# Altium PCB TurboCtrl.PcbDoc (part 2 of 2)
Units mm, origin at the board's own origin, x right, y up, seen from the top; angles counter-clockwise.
Board outline 40.25 x 40.25 mm, 4 copper layers (Top Layer, GND, SIGNAL, Bottom Layer), stack 1.571 mm thick; 111 components, 99 nets, 426 pads, 163 vias.
Unrouted connection lines stored in the file: 47.
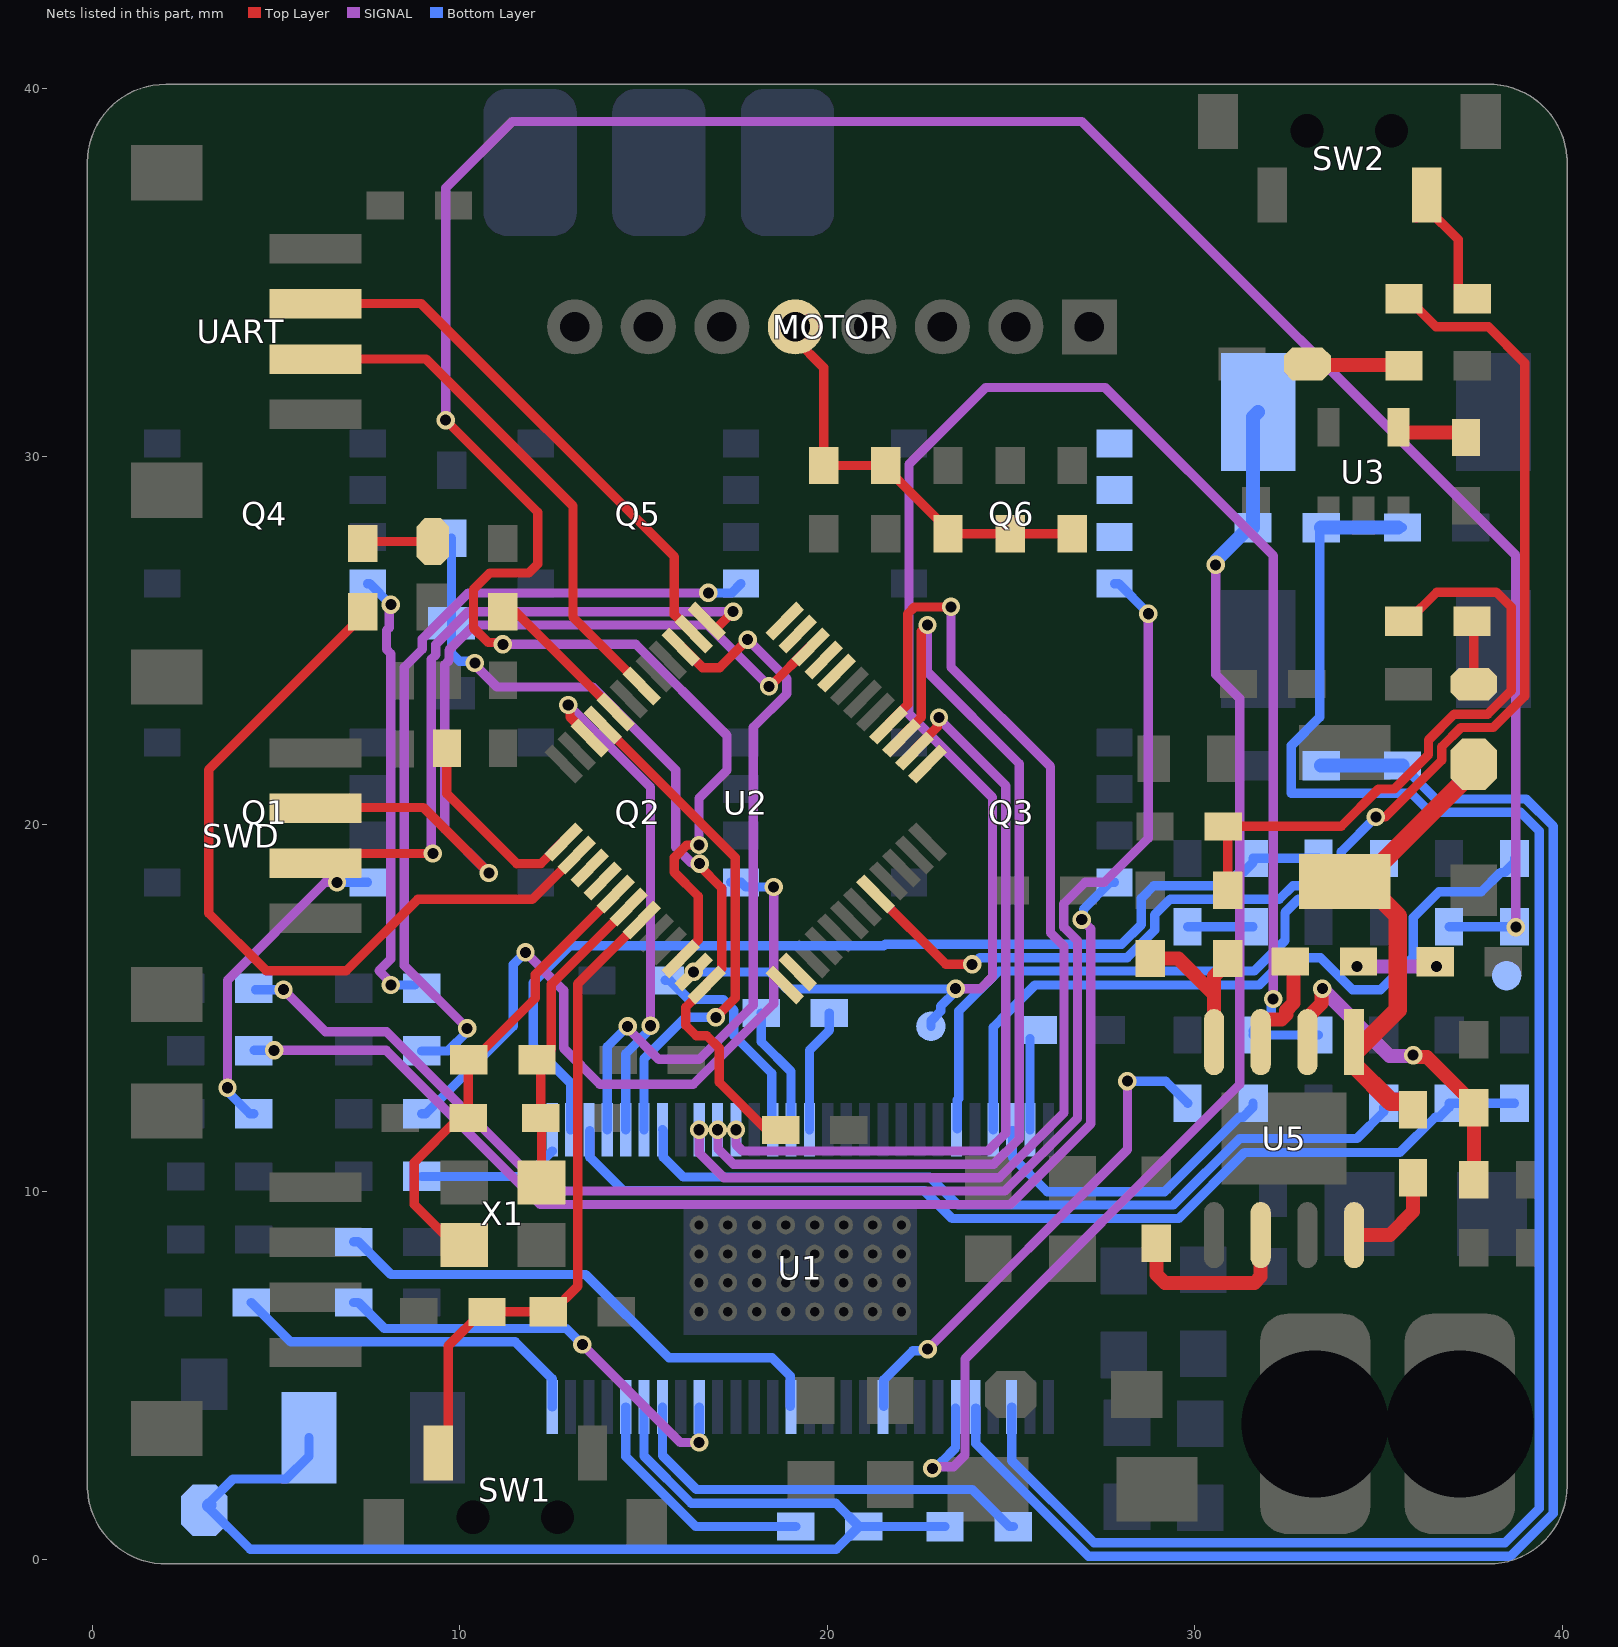
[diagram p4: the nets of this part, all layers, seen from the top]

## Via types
v1: diameter 0.5, hole 0.3, Top Layer to Bottom Layer, tented both sides, 163 vias

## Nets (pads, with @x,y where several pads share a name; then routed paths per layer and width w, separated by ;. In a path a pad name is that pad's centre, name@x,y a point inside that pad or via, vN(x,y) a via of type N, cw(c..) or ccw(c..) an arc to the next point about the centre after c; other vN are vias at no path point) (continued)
M_C_Current: Q6.S R23.2 R24.1 U1.34 | length 35.3
  SIGNAL w0.254: v1(22.86,2.471) 22.907,2.518 23.433,2.518 23.749,2.834 23.749,5.449 31.221,12.921 31.221,23.416 30.569,24.068 v1(30.569,27.051)
  Bottom Layer w0.254: v1(22.86,2.471) 22.927,2.471 23.121,2.666 23.127,2.666 23.49,3.029 U1.34@23.49,4.115
  Bottom Layer w0.381: v1(30.569,27.051) 30.592,27.074 30.592,27.182 31.477,28.067 R24.1@31.585,28.067 31.585,31.071 R23.2@31.725,31.211
MSPI_SCLK: U1.11 U2.26 | length 21.2
  Top Layer w0.254: U2.26@22.376,22.024 22.994,22.642 22.994,22.854 v1(23.041,22.902)
  SIGNAL w0.254: v1(17.516,11.684) 17.516,11.286 17.694,11.108 24.375,11.108 24.859,11.592 24.859,21.047 23.041,22.865 v1(23.041,22.902)
MSPI_SDI: U1.9 U2.28 | length 31.1
  Top Layer w0.254: U2.28@21.669,22.695 21.669,22.731 22.19,23.252 22.19,25.724 22.374,25.908 v1(23.368,25.908)
  SIGNAL w0.254: v1(16.516,11.684) 16.517,11.682 16.517,11.053 17.19,10.38 24.677,10.38 26.442,12.145 26.442,16.677 26.073,17.047 26.073,21.564 23.368,24.269 v1(23.368,25.908)
MSPI_SDO: U1.10 U2.27 | length 27.6
  Top Layer w0.254: U2.27@22.023,22.342 22.023,22.378 22.554,22.909 22.554,25.245 v1(22.726,25.417)
  SIGNAL w0.254: v1@17.029,11.671 17.029,11.166 17.451,10.744 24.526,10.744 25.223,11.441 25.223,21.64 22.726,24.137 v1(22.726,25.417)
  Bottom Layer w0.254: v1(17.016,11.684) U1.10@17.041,11.709
NetC2_1: C2.1 R8.1 U1.2 | length 27.7
  Bottom Layer w0.254: U1.2@13.016,11.684 13.016,12.954 12,13.97 12,15.683 13.004,16.687 21.538,16.687 21.581,16.73 28.007,16.73 28.546,17.269 28.546,17.983 28.883,18.319 30.84,18.319 31.204,18.684 31.312,18.684 31.585,18.957 R8.1@31.585,19.065 ; R8.1@31.585,19.07 C2.1@33.363,19.07
NetC5_1: C5.1 R8.2 | length 1.8
  Bottom Layer w0.254: C5.1@29.807,17.21 R8.2@31.585,17.21
NetC6_2: C6.2 U1.56 | length 9.8
  Bottom Layer w0.254: C6.2@4.33,6.985 5.402,5.913 11.509,5.913 12.516,4.906 U1.56@12.516,4.14
NetC7_1: C7.1 D1.2 L1.1 R16.1 U1.51 | length 32.6
  Bottom Layer w0.254: D1.2@3.175,1.46 3.175,1.397 4.301,0.271 20.248,0.271 C7.1@20.866,0.889 ; D1.2@3.175,1.524 3.832,2.181 5.278,2.181 5.901,2.804 L1.1@5.901,3.304 ; U1.51@15.016,4.14 15.016,2.809 16.301,1.524 20.231,1.524 C7.1@20.866,0.889 ; R16.1@23.203,0.889 C7.1@20.993,0.889 C7.1@20.866,0.889
  Bottom Layer w0.381: D1.2@3.175,1.46 D1.2@3.195,1.48
NetC7_2: C7.2 U1.52 | length 6.8
  Bottom Layer w0.254: U1.52@14.516,4.14 14.516,2.794 16.421,0.889 C7.2@19.139,0.889
NetC8_2: C8.2 U1.48 | length 11.9
  SIGNAL w0.254: v1(13.335,5.842) 16.002,3.175 v1(16.513,3.175)
  Bottom Layer w0.254: C8.2@7.117,6.985 7.244,6.985 7.952,6.277 12.9,6.277 v1(13.335,5.842) ; v1(16.513,3.175) 16.514,3.176 U1.48@16.514,4.139
NetC9_2: C9.2 U1.43 | length 14.2
  Bottom Layer w0.254: C9.2@7.117,8.636 7.244,8.636 8.133,7.747 13.425,7.747 15.694,5.478 18.497,5.478 18.991,4.985 U1.43@18.991,4.166
NetC10_1: C10.1 U1.13 | length 5.9
  Bottom Layer w0.254: C10.1@15.589,15.748 15.716,15.748 16.236,15.228 17.171,15.228 17.459,14.94 17.459,14.255 18.491,13.224 U1.13@18.491,11.709
NetC11_1: C11.1 U1.14 | length 3.5
  Bottom Layer w0.254: C11.1@18.204,14.859 18.204,14.081 19.016,13.269 U1.14@19.016,11.684
NetC11_2: C11.2 U1.15 | length 3.4
  Bottom Layer w0.254: U1.15@19.516,11.684 19.516,13.851 20.059,14.393 C11.2@20.059,14.859
NetC12_2: C12.2 U1.38 | length 13.7
  SIGNAL w0.254: v1(22.733,5.715) 28.167,11.149 v1(28.167,13.005)
  Bottom Layer w0.254: U1.38@21.541,4.166 21.541,4.884 22.325,5.668 22.686,5.668 v1(22.733,5.715) ; v1(28.167,13.005) 29.21,13.005 C12.2@29.807,12.408
NetC13_2: C13.2 U1.23 | length 17
  Bottom Layer w0.254: U1.23@23.541,11.709 23.541,12.494 23.58,12.532 23.58,14.914 24.668,16.002 31.62,16.002 32.451,16.834 32.451,17.592 32.82,17.961 34.038,17.961 34.76,18.684 34.887,18.684 35.141,18.938 C13.2@35.141,19.065
NetC14_2: C14.2 R20.2 U1.33 | length 44.1
  Bottom Layer w0.254: U1.33@24.041,4.115 24.041,3.148 27.107,0.082 38.588,0.082 39.751,1.245 39.751,19.946 39.013,20.684 36.555,20.684 C14.2@35.649,21.59
  Bottom Layer w0.381: R20.2@33.439,21.59 C14.2@35.649,21.59
NetC15_1: C15.1 U1.27 | length 2.5
  Bottom Layer w0.254: U1.27@25.516,11.684 C15.1@25.516,14.166
NetC16_2: C16.2 R24.2 U1.31 | length 52.4
  Bottom Layer w0.254: U1.31@25.016,4.14 25.016,2.688 27.258,0.446 38.437,0.446 39.37,1.379 39.37,19.812 38.862,20.32 36.404,20.32 35.885,20.839 32.628,20.839 32.628,22.138 33.401,22.911 R24.2@33.401,28.029 ; C16.2@35.522,28.067 C16.2@35.649,28.067
  Bottom Layer w0.381: R24.2@33.439,28.067 C16.2@35.522,28.067
NetC31_1: C31.1 U3.4 | length 1.8
  Top Layer w0.381: U3.4@35.537,30.791 35.537,30.764 35.646,30.655 C31.1@37.245,30.655
NetC32_1: C32.1 D2.2 L2.1 U5.1 | length 12.2
  Top Layer w0.5: C32.1@35.941,12.255 35.75,12.446 35.332,12.446 34.333,13.445 34.333,13.759 35.526,14.952 35.526,17.496 34.579,18.443 D2.2@37.592,21.456
NetC32_2: C32.2 U5.8 | length 2.8
  Top Layer w0.381: U5.8@34.333,8.82 35.306,8.82 35.941,9.455 C32.2@35.941,10.376
NetC38_1: C38.1 R26.2 R34.1 | length 16.8
  Top Layer w0.254: R34.1@30.899,18.199 C38.1@30.899,19.812 ; C38.1@30.899,19.939 33.982,19.939 34.999,20.956 35.427,20.956 36.356,21.885 36.356,22.289 37.059,22.992 37.968,22.992 38.608,23.632 38.608,25.908 38.205,26.311 36.582,26.311 35.795,25.524 R26.2@35.687,25.524
NetC39_1: C39.1 R38.1 | length 2.3
  Top Layer w0.381: v1(34.417,16.129) 34.417,16.218 C39.1@34.455,16.256
  SIGNAL w0.381: v1(34.417,16.129) v1(36.576,16.129)
NetC39_2: C39.2 U5.3 | length 2.9
  Top Layer w0.381: U5.3@31.793,14.07 31.793,14.611 31.871,14.69 32.359,14.69 32.488,14.818 32.488,14.933 32.681,15.127 32.681,16.175 C39.2@32.601,16.256
NetLED1_2: LED1.2 R26.1 | length 1.7
  Top Layer w0.254: LED1.2@37.592,23.808 R26.1@37.592,25.473
NetLED2_2: LED2.2 R28.2 | length 1.9
  Top Layer w0.254: R28.2@7.366,27.635 7.417,27.686 LED2.2@9.264,27.686
NetLED3_2: LED3.2 R31.1 | length 2.6
  Top Layer w0.381: LED3.2@33.063,32.519 33.089,32.493 R31.1@35.666,32.493
NetMOTOR_5: MOTOR.5 R2.2 R3.2 R5.1 R6.1 R7.1 | length 11.3
  Top Layer w0.254: MOTOR.5@19.132,33.191 19.901,32.421 R3.2@19.901,29.756 21.485,29.756 21.866,29.375 21.92,29.375 23.394,27.902 R6.1@24.978,27.902 R7.1@26.67,27.902
NetQ1_G: Q1.G R11.1 | length 8.8
  SIGNAL w0.254: v1(3.683,12.827) 3.683,15.755 6.343,18.415 v1(6.663,18.415)
  Bottom Layer w0.254: v1@3.73,12.78 3.73,12.679 4.291,12.118 R11.1@4.399,12.118 ; v1(6.663,18.415) Q1.G@7.494,18.415
NetQ2_G: Q2.G R12.1 | length 20.1
  SIGNAL w0.254: v1(11.792,16.51) 12.827,15.475 12.827,13.905 13.812,12.92 16.352,12.92 18.542,15.11 v1(18.542,18.288)
  Bottom Layer w0.254: R12.1@8.971,12.118 9.079,12.118 11.46,14.498 11.46,16.178 v1(11.792,16.51) ; Q2.G@17.379,18.415 Q2.G@17.654,18.415 17.781,18.288 v1(18.542,18.288)
NetQ3_G: Q3.G R13.1 | length 32.5
  SIGNAL w0.254: v1(4.953,13.843) 8.001,13.843 12.192,9.652 24.978,9.652 27.17,11.844 27.17,17.153 v1(26.924,17.399)
  Bottom Layer w0.254: R13.1@4.414,13.843 v1(4.953,13.843) ; v1(26.924,17.399) 26.971,17.446 26.971,17.686 27.7,18.415 Q3.G@27.814,18.415
NetQ4_G: Q4.G R17.1 | length 12.2
  SIGNAL w0.254: v1@8.128,15.688 7.808,16.008 8.128,16.328 8.128,24.634 8.008,24.754 8.008,25.268 8.081,25.341 8.081,25.922 v1(8.128,25.969)
  Bottom Layer w0.254: Q4.G@7.494,26.543 7.554,26.543 v1(8.128,25.969) ; v1(8.128,15.621) R17.1@8.781,15.621
NetQ5_G: Q5.G R18.1 | length 22.4
  SIGNAL w0.254: v1(10.204,14.443) 8.492,16.155 8.492,24.264 8.982,24.754 8.982,25.036 10.235,26.289 v1(16.764,26.289)
  Bottom Layer w0.254: R18.1@8.971,13.828 9.681,13.828 10.204,14.351 v1(10.204,14.443) ; v1@16.764,26.356 v1(16.764,26.289) 17.4,26.289 Q5.G@17.654,26.543
NetQ6_G: Q6.G R19.1 | length 41.9
  SIGNAL w0.254: v1(5.207,15.494) 6.35,14.351 8.008,14.351 12.343,10.016 24.827,10.016 26.806,11.995 26.806,16.828 26.437,17.197 26.437,17.834 27.018,18.415 27.534,18.415 28.735,19.616 v1(28.735,25.723)
  Bottom Layer w0.254: R19.1@4.444,15.494 v1(5.207,15.494) ; Q6.G@27.814,26.543 27.928,26.543 28.735,25.736 v1(28.735,25.723)
NetR1_1: R1.1 SW2.2 | length 3.5
  Top Layer w0.254: SW2.2@36.033,36.489 36.306,36.762 37.165,35.903 37.165,34.563 37.438,34.29 R1.1@37.546,34.29 R1.1@37.617,34.29
NetR9_2: R9.2 U1.1 | length 3.8
  Bottom Layer w0.254: R9.2@8.971,10.414 11.825,10.414 U1.1@12.516,11.105
NetR10_2: R10.2 R14.1 U1.3 | length 27.9
  Bottom Layer w0.254: U1.3@13.541,11.659 13.541,10.94 14.448,10.033 22.635,10.033 23.397,9.271 29.56,9.271 31.355,11.066 35.577,11.066 36.538,12.027 36.646,12.027 36.919,12.3 R10.2@36.919,12.408 R14.1@38.697,12.408
NetR15_2: R15.2 U1.7 | length 22.1
  Bottom Layer w0.254: U1.7@15.516,11.684 15.541,11.659 15.541,10.94 16.084,10.397 22.786,10.397 23.548,9.635 29.409,9.635 31.221,11.447 34.412,11.447 35.141,12.176 R15.2@35.141,12.3
NetR16_2: R16.2 U1.50 | length 11.7
  Bottom Layer w0.254: U1.50@15.516,4.14 15.516,2.824 16.444,1.895 23.943,1.895 24.949,0.889 R16.2@25.057,0.889
NetR21_2: R21.2 U1.25 | length 20.3
  Bottom Layer w0.254: U1.25@24.516,11.684 24.516,14.472 24.744,14.7 24.744,14.711 25.654,15.621 31.753,15.621 32.498,16.366 33.418,16.366 34.29,15.494 35.052,15.494 35.941,16.383 35.941,17.457 36.645,18.161 37.793,18.161 38.316,18.684 38.424,18.684 38.697,18.957 R21.2@38.697,19.065
NetR25_2: R25.2 U1.26 | length 8.7
  Bottom Layer w0.254: U1.26@25.041,11.659 25.041,10.94 25.982,9.999 29.176,9.999 31.204,12.027 31.312,12.027 31.585,12.3 R25.2@31.585,12.408
NetR29_2: R29.2 U2.44 | length 4.2
  Top Layer w0.254: R29.2@11.176,25.781 11.512,25.781 U2.44@14.244,23.049
NetR32_1: R32.1 R36.2 U5.2 | length 8.5
  Top Layer w0.381: U5.2@33.063,14.741 33.445,15.122 33.445,15.498 v1(33.467,15.521) ; v1(35.941,13.716) 35.941,13.669 36.312,13.669 37.592,12.389 R36.2@37.592,12.281 R32.1@37.592,10.325
  SIGNAL w0.381: v1(33.467,15.521) 35.295,13.693 35.918,13.693 v1(35.941,13.716)
NetR34_2: R34.2 R35.1 U5.4 | length 4.5
  Top Layer w0.381: R35.1@28.791,16.345 28.791,16.337 29.553,16.337 30.523,15.367 ; U5.4@30.523,14.07 30.523,15.367 ; R34.2@30.899,16.237 30.523,15.861 30.523,15.367
NetR37_2: R37.2 U5.6 | length 4.4
  Top Layer w0.381: R37.2@28.956,8.598 28.956,7.747 29.185,7.518 31.618,7.518 31.793,7.694 U5.6@31.793,8.195
NetU2_3: U2.3
NetU2_4: U2.4
NetU2_13: U2.13
NetU2_14: U2.14
NetU2_25: U2.25
NetU2_32: U2.32
NetU2_33: U2.33
NetU2_35: U2.35
NetU2_36: U2.36
nFAULT: U1.6 U2.45 | length 14.1
  Top Layer w0.254: U2.45@13.891,22.695 17.497,19.09 17.497,15.268 v1(16.97,14.741)
  Bottom Layer w0.254: U1.6@15.016,11.684 15.016,13.619 16.137,14.741 16.858,14.741 16.914,14.685 v1(16.97,14.741)
nOCTW: U1.5 U2.46 | length 13.9
  Top Layer w0.254: v1(12.954,23.241) 13.001,23.194 13.001,22.914 U2.46@13.537,22.378
  SIGNAL w0.254: v1(12.954,23.241) 15.191,21.004 v1(15.191,14.513)
  Bottom Layer w0.254: U1.5@14.516,11.684 14.516,13.754 15.191,14.43 v1(15.191,14.513)
NRST: C24.2 R30.1 SW1.2 U2.7 | length 18.2
  Top Layer w0.254: SW1.2@9.412,2.893 9.685,3.166 9.685,5.799 C24.2@10.617,6.731 ; C24.2@10.744,6.731 R30.1@12.408,6.731 12.516,6.731 13.208,7.423 13.208,15.648 U2.7@14.952,17.392 ; R30.1@12.319,6.47 12.548,6.699 R30.1@12.408,6.699
OSC_IN: C20.1 R27.1 U2.5 X1.3 | length 12.7
  Top Layer w0.254: X1.3@10.076,8.548 9.867,8.548 8.763,9.652 8.763,10.795 9.976,12.008 C20.1@10.236,12.008 R27.1@10.236,13.576 ; R27.1@10.249,13.589 10.382,13.589 12.056,15.262 12.056,15.91 U2.5@14.244,18.099
OSC_OUT: C22.1 R27.2 U2.6 X1.1 | length 8.5
  Top Layer w0.254: R27.2@12.103,13.589 12.211,13.589 12.495,13.873 12.495,15.642 U2.6@14.598,17.746 ; C22.1@12.205,12.008 R27.2@12.205,13.487 ; X1.1@12.226,10.248 C22.1@12.226,11.987
PB2: R1.2 U2.20 | length 35.3
  Top Layer w0.254: U2.20@21.316,18.099 23.228,16.186 v1(23.943,16.186) ; v1(34.925,20.193) 35.179,20.193 36.72,21.734 36.72,22.107 37.241,22.628 38.119,22.628 38.972,23.481 38.972,32.545 37.989,33.528 36.562,33.528 R1.2@35.8,34.29
  Bottom Layer w0.254: v1@23.943,16.163 v1(23.943,16.186) ; v1@24.013,16.234 24.146,16.366 28.158,16.366 28.91,17.118 28.91,17.538 29.328,17.955 32.3,17.955 32.669,18.325 33.842,18.325 33.981,18.464 33.981,19.249 v1(34.925,20.193)
PC13: R28.1 U2.2 | length 21.8
  Top Layer w0.254: R28.1@7.366,25.673 3.175,21.482 3.175,17.574 4.742,16.007 6.915,16.007 8.858,17.951 11.975,17.951 U2.2@13.184,19.16
PWRGD: U1.4 U2.39 | length 20.6
  Top Layer w0.254: U2.39@16.048,24.817 16.608,24.257 17.073,24.257 v1(17.835,25.019)
  SIGNAL w0.254: v1(14.571,14.498) 14.571,14.445 15.412,13.604 16.521,13.604 17.989,15.071 17.989,22.633 18.902,23.546 18.902,23.952 v1(17.835,25.019)
  Bottom Layer w0.254: U1.4@14.016,11.684 14.016,13.943 v1(14.571,14.498)
SO1: C18.1 R21.1 TP5.1 U2.10 | length 76.4
  Top Layer w0.254: v1(9.618,30.988) 12.121,28.485 12.121,27.074 11.877,26.83 10.818,26.83 10.376,26.388 10.376,25.338 10.775,24.939 11.129,24.939 v1(11.176,24.892) ; U2.10@16.012,16.331 16.012,16.367 16.493,16.848 16.493,18.034 15.841,18.686 15.841,19.092 16.181,19.431 v1(16.51,19.431)
  SIGNAL w0.254: v1(9.618,30.988) 9.618,37.304 11.43,39.116 26.924,39.116 38.735,27.305 v1(38.735,17.197) ; v1(11.176,24.892) 14.789,24.892 17.272,22.409 17.272,21.463 16.51,20.701 v1(16.51,19.431)
  Bottom Layer w0.254: C18.1@36.919,17.21 R21.1@38.697,17.21
SO2: C19.1 R25.1 TP6.1 U2.11 | length 52.2
  SIGNAL w0.254: v1(23.495,15.521) 24.174,15.521 24.495,15.842 24.495,20.725 22.225,22.995 22.225,29.79 24.312,31.877 27.559,31.877 32.131,27.305 v1(32.131,15.24)
  Bottom Layer w0.254: v1(16.366,15.978) 18.436,15.978 18.899,15.515 v1@23.495,15.515 ; TP6.1@22.821,14.498 22.821,14.646 23.089,14.914 23.089,15.048 v1@23.495,15.454 ; R25.1@31.585,14.262 C19.1@33.363,14.262 ; R25.1@31.585,14.37 32.084,14.869 32.084,15.193 v1(32.131,15.24)
SWDCLK: SWD.3 U2.37 | length 19.1
  Top Layer w0.254: SWD.3@5.097,19.201 6.336,19.201 v1(9.271,19.201) ; U2.37@16.934,25.309 16.97,25.309 v1(17.441,25.781)
  SIGNAL w0.254: v1@9.228,19.201 9.228,24.485 9.346,24.603 9.346,24.885 10.242,25.781 v1(17.441,25.781)
SWDIO: SWD.2 U2.34 | length 24.3
  Top Layer w0.254: SWD.2@5.097,20.451 6.336,20.451 9.013,20.451 v1(10.795,18.669) ; v1@18.448,23.749 19.515,24.817 U2.34@19.548,24.817
  SIGNAL w0.254: v1(10.795,18.669) 9.592,19.872 9.592,24.335 9.71,24.452 9.71,24.734 10.393,25.417 16.747,25.417 v1(18.415,23.749)
TEMP: C1.1 R4.1 RT.1 U2.12 | length 22.8
  Top Layer w0.254: v1@16.495,18.891 17.133,18.253 17.133,16.073 16.719,15.66 U2.12@16.719,15.624 16.719,15.588 16.15,15.019 16.15,14.53 16.435,14.245 16.723,14.245 17.061,13.907 17.061,12.973 18.35,11.684 C1.1@18.732,11.684
  SIGNAL w0.254: v1(10.414,24.384) 10.414,24.329 11.015,23.728 13.62,23.728 15.875,21.473 15.875,19.373 16.304,18.944 v1@16.507,18.944
  Bottom Layer w0.254: R4.1@9.779,27.775 RT.1@9.779,25.461 9.779,24.645 9.993,24.431 v1@10.367,24.431
  other v1: 16.528,18.923
USART1_RX: U2.38 UART.2 | length 14.9
  Top Layer w0.254: UART.2@6.094,34.163 8.95,34.163 15.841,27.272 15.841,25.695 U2.38@16.366,25.17
USART1_TX: U2.42 UART.3 | length 14.3
  Top Layer w0.254: UART.3@6.082,32.651 9.085,32.651 13.081,28.655 13.081,25.627 U2.42@14.952,23.756
VBAT: C26.2 U2.1 | length 5.4
  Top Layer w0.254: C26.2@9.652,22.06 9.652,20.828 11.557,18.923 12.204,18.923 U2.1@12.794,19.513
pads on no net: I2C.0 SW1.0 SW2.0 SWD.0 U1.55 U1.V U5.9 U5.10 U5.11 UART.0 X1.2 X1.4
copper on no net: | length 3.9
  Bottom Layer w0.254: 20.447,9.093 21.234,9.093 22.022,9.093
  Bottom Layer w0.381: 16.51,9.093 17.297,9.093 18.085,9.093 18.872,9.093
  other v1: 34.479,9.398 14.732,15.122

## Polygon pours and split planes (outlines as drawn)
GND on Bottom Layer "GND_L04_P002" (solid, remove dead copper, pour order 2): 2.032,40.005 ccw(c2.032,37.973) 0,37.973 0,2.413 ccw(c2.413,2.413) 2.413,0 38.1,0 ccw(c38.1,1.905) 40.005,1.905 40.005,38.079 ccw(c38.079,38.079) 38.079,40.005
GND on Top Layer "GND_L01_P000" (solid, remove dead copper, pour order 0): 0.127,38.869 0.127,2.159 ccw(c2.286,2.159) 2.286,0 37.846,0 ccw(c37.846,2.159) 40.005,2.159 40.005,37.968 ccw(c37.968,37.968) 37.968,40.005 1.736,40.005 ccw(c2.772,35.923) 0.762,39.624 ccw(c3.46,36.709)
GND on GND (split plane): 0.368,0.63 0.442,0.549 0.359,0.633 0.294,0.727
GND on GND (split plane): 0.63,0.368 0.727,0.294 0.633,0.359 0.549,0.442
GND on GND (split plane): -0.002,1.271 0.029,1.196 -0.02,1.305 -0.045,1.407
GND on GND (split plane): 0.155,0.935 0.207,0.853 0.139,0.952 0.094,1.052
GND on GND (split plane): 1.271,-0.002 1.407,-0.045 1.305,-0.02 1.196,0.029
GND on GND (split plane): 1.63,-0.098 1.781,-0.118 1.681,-0.112 1.571,-0.085
GND on GND (split plane): 2.001,40.126 38.105,40.126 38.138,40.119 38.138,40.122 38.139,40.122 38.138,40.12 38.185,40.118 38.369,40.093 38.55,40.053 38.727,39.997 38.898,39.926 39.063,39.841 39.219,39.741 39.366,39.628 39.503,39.503 39.628,39.366 39.741,39.219 39.841,39.063 39.926,38.898 39.997,38.727 40.053,38.55 40.093,38.369 40.118,38.185 40.12,38.138 40.122,38.139 40.122,38.138 40.119,38.138 40.126,38.105 40.126,2 40.118,1.815 40.093,1.631 40.053,1.45 39.997,1.273 39.926,1.102 39.841,0.937 39.741,0.781 39.628,0.634 39.503,0.497 39.366,0.372 39.219,0.259 39.063,0.159 38.898,0.074 38.727,0.003 38.55,-0.053 38.369,-0.093 38.185,-0.118 38,-0.126 1.905,-0.126 1.875,-0.12 1.875,-0.122 1.875,-0.12 1.815,-0.118 1.631,-0.093 1.45,-0.053 1.273,0.003 1.102,0.074 0.937,0.159 0.781,0.259 0.634,0.372 0.497,0.497 0.372,0.634 0.259,0.781 0.159,0.937 0.074,1.102 0.003,1.273 -0.053,1.45 -0.093,1.631 -0.118,1.815 -0.12,1.875 -0.122,1.875 -0.12,1.875 -0.126,1.905 -0.126,38 -0.118,38.185 -0.093,38.369 -0.053,38.55 0.003,38.727 0.074,38.898 0.159,39.063 0.259,39.219 0.372,39.366 0.497,39.503 0.634,39.628 0.781,39.741 0.937,39.841 1.102,39.926 1.273,39.997 1.45,40.053 1.631,40.093 1.815,40.118 2,40.126 2.001,40.126
GND on GND (split plane): 0.935,0.155 1.052,0.094 0.952,0.139 0.853,0.207
GND on GND (split plane): -0.123,38.186 -0.127,38.076 -0.127,38.21 -0.104,38.328
GND on GND (split plane): -0.098,1.63 -0.085,1.571 -0.112,1.681 -0.118,1.781
GND on GND (split plane): -0.058,38.551 -0.071,38.495 -0.046,38.621 -0.007,38.715
GND on GND (split plane): 0.155,39.065 0.076,38.913 0.115,39.008 0.186,39.114
GND on GND (split plane): 0.368,39.37 0.281,39.256 0.348,39.356 0.442,39.451
GND on GND (split plane): 0.63,39.632 0.549,39.558 0.644,39.652 0.744,39.719
GND on GND (split plane): 0.935,39.845 0.886,39.814 0.992,39.885 1.087,39.924
GND on GND (split plane): 1.449,40.058 1.285,40.007 1.379,40.046 1.505,40.071
GND on GND (split plane): 38.21,-0.127 38.076,-0.127 38.186,-0.123 38.328,-0.104
GND on GND (split plane): 38.621,-0.046 38.495,-0.071 38.551,-0.058 38.715,-0.007
GND on GND (split plane): 39.008,0.115 38.913,0.076 39.065,0.155 39.114,0.186
GND on GND (split plane): 39.356,0.348 39.256,0.281 39.37,0.368 39.451,0.442
GND on GND (split plane): 39.652,0.644 39.558,0.549 39.632,0.63 39.719,0.744
GND on GND (split plane): 39.885,0.992 39.814,0.886 39.845,0.935 39.924,1.087
GND on GND (split plane): 40.046,1.379 40.007,1.285 40.058,1.449 40.071,1.505
GND on GND (split plane): 40.127,1.79 40.104,1.672 40.123,1.814 40.127,1.924
GND on GND (split plane): 38.703,40.017 38.811,39.968 38.729,40.002 38.599,40.043
GND on GND (split plane): 39.053,39.859 39.15,39.791 39.065,39.845 38.952,39.904
GND on GND (split plane): 1.814,40.123 1.672,40.104 1.79,40.127 1.924,40.127
GND on GND (split plane): 38.33,40.11 38.443,40.082 38.37,40.098 38.228,40.117
GND on GND (split plane): 40.017,38.703 40.043,38.599 40.002,38.729 39.968,38.811
GND on GND (split plane): 40.11,38.33 40.117,38.228 40.098,38.37 40.082,38.443
GND on GND (split plane): 39.369,39.64 39.451,39.558 39.37,39.632 39.275,39.705
GND on GND (split plane): 39.859,39.053 39.904,38.952 39.845,39.065 39.791,39.15
GND on GND (split plane): 39.64,39.368 39.705,39.275 39.632,39.37 39.558,39.451

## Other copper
Top Layer:
  region net DCBUS: 28.448,3.048 30.353,3.048 ccw(c30.353,3.302) 30.607,3.302 30.607,4.432 ccw(c30.353,4.432) 30.353,4.686 29.464,4.686 29.464,3.835 cw(c29.185,3.835) 29.185,3.556 28.448,3.556 ccw(c28.448,3.302) 28.194,3.302 ccw(c28.448,3.302)
  region net DCBUS: 25.273,1.016 ccw(c25.273,2.667) 26.924,2.667 26.924,4.445 cw(c27.813,4.445) 27.813,5.334 29.185,5.334 cw(c29.185,5.055) 29.464,5.055 29.464,4.318 ccw(c29.591,4.318) 29.591,4.191 30.353,4.191 ccw(c30.353,4.445) 30.607,4.445 30.607,6.216 ccw(c30.353,6.216) 30.353,6.47 27.185,6.47 cw(c27.185,6.604) 27.051,6.604 ccw(c26.797,6.604) 26.797,6.858 25.781,6.858 cw(c25.781,7.62) 25.019,7.62 25.019,10.668 ccw(c24.765,10.668) 24.765,10.922 23.876,10.922 ccw(c23.876,10.795) 23.749,10.795 23.749,5.77 cw(c22.987,5.77) 22.987,5.008 19.232,5.008 ccw(c19.232,4.699) 18.923,4.699 18.923,3.892 ccw(c19.132,3.892) 19.132,3.683 22.905,3.683 cw(c22.905,3.302) 23.286,3.302 23.286,1.016
SIGNAL:
  region net DCBUS: 30.367,6.477 cw(c30.353,6.223) 30.607,6.223 30.607,3.302 cw(c30.353,3.302) 30.353,3.048 26.416,3.048 26.405,4.699 ccw(c26.024,4.699) 26.024,5.08 25.89,5.08 cw(c25.862,5.311) 25.654,5.207 25.654,6.8 26.715,6.897
  region net M_C: 25.908,31.115 cw(c25.864,30.963) 26.016,31.007 26.016,29.326 ccw(c26.259,29.326) 26.259,29.083 26.289,29.083 cw(c26.289,28.829) 26.543,28.829 26.543,24.743 cw(c25.251,21.874) 28.194,22.987 28.194,19.558 cw(c27.837,19.558) 27.837,19.201 27.027,19.201 cw(c27.027,19.558) 26.67,19.558 26.67,21.414 ccw(c24.423,21.414) 24.423,23.661 cw(c25.744,24.982) 23.889,24.764 23.878,31.048 cw(c23.971,31.021) 23.945,31.115
Bottom Layer:
  region net M_C: 28.304,22.606 28.304,19.454 cw(c28.154,19.454) 28.154,19.304 26.941,19.304 cw(c26.941,19.448) 26.797,19.448 26.797,22.391 cw(c27.012,22.391) 27.012,22.606
  region net DCBUS: 14.179,2.432 cw(c13.779,2.432) 13.779,2.032 13.208,2.032 cw(c13.208,2.224) 13.016,2.224 13.016,2.921 13.081,2.921 ccw(c13.081,3.175) 13.335,3.175 13.335,4.826 cw(c13.399,4.826) 13.399,4.889 14.115,4.889 cw(c14.115,4.826) 14.179,4.826
  region net DCBUS: 25.898,3.125 25.743,5.334 25.655,6.593 cw(c25.899,6.613) 25.89,6.858 30.861,6.858 cw(c30.861,6.731) 30.988,6.731 30.988,2.921 cw(c30.734,2.921) 30.734,2.667 27.918,2.667
  region net M_A: 8.001,19.304 8.001,22.902 ccw(c5.461,22.902) 7.257,24.698 6.19,25.764 cw(c6.588,26.162) 6.026,26.162 ccw(c5.549,26.162) 5.886,26.499 5.715,26.67 ccw(c5.102,26.057) 5.102,26.924 1.704,26.924 ccw(c1.704,26.49) 1.397,26.797 1.397,25.489 ccw(c2.79,25.489) 1.805,24.504 2.206,24.103 ccw(c3.75,25.647) 3.75,23.463 5.256,23.463 cw(c5.256,21.837) 6.406,22.987 cw(c5.007,21.589) 6.985,21.588 6.985,19.304
  region: 18.155,19.304 18.161,19.31 ccw(c15.896,22.606) 17.498,24.207 16.64,25.065 cw(c17.737,26.162) 16.186,26.162 16.186,29.957 ccw(c14.746,29.957) 15.764,30.975 ccw(c15.533,30.744) 15.533,31.071 12.495,31.071 ccw(c12.495,30.716) 12.244,30.967 ccw(c12.417,30.794) 12.172,30.794 12.172,26.162 ccw(c13.134,26.162) 12.454,25.482 13.76,24.176 ccw(c15.245,25.661) 15.245,23.561 cw(c15.245,22.349) 16.101,23.206 16.46,22.847 cw(c14.746,21.133) 17.17,21.133 17.17,19.304
  region net M_B_Current: 17.166,30.698 18.571,30.698 cw(c18.571,29.21) 20.059,29.21 20.059,27.686 ccw(c22.599,27.686) 22.599,25.146 29.25,25.146 ccw(c29.25,25.868) 29.972,25.868 29.972,25.921 cw(c30.37,25.921) 30.37,26.319 32.228,26.319 cw(c32.165,25.845) 32.639,25.781 32.639,23.561 cw(c32.225,23.655) 32.131,23.241 20.468,23.241 cw(c20.04,24.453) 18.796,24.13 18.228,27.284 17.159,27.432
  region net M_C_Current: 27.305,30.823 cw(c27.559,30.823) 27.559,31.077 28.154,31.077 ccw(c28.154,32.603) 29.68,32.603 cw(c29.88,32.603) 29.88,32.802 31.585,32.802 cw(c31.585,32.383) 32.004,32.383 32.004,30.213 cw(c31.421,30.213) 31.421,29.629 30.734,29.629 ccw(c30.734,28.613) 29.718,28.613 29.718,27.051 cw(c29.242,27.146) 29.146,26.67 28.732,26.748 28.067,27.178 cw(c27.999,28.227) 27.305,27.437 cw(c27.606,27.562) 27.305,27.686
  region net M_C: 17.116,32.766 cw(c17.116,33.499) 16.383,33.499 16.383,34.042 cw(c17.456,34.042) 17.456,35.115 ccw(c17.456,35.321) 17.662,35.321 17.662,36.736 cw(c17.883,36.736) 17.883,36.957 19.939,36.957 cw(c19.939,36.703) 20.193,36.703 20.193,35.542 cw(c19.132,35.542) 19.132,34.481 18.934,34.481 ccw(c18.922,33.442) 17.887,33.532 cw(c17.138,33.518) 17.152,32.77 17.132,32.766
  region net M_B: 15.12,32.785 15.133,32.785 ccw(c15.133,33.527) 15.875,33.527 16.004,34.879 cw(c16.319,34.935) 16.263,35.25 ccw(c16.263,35.683) 16.697,35.683 16.697,36.614 ccw(c16.519,36.614) 16.519,36.792 14.231,36.792 ccw(c14.231,36.722) 14.161,36.722 14.161,35.554 ccw(c14.315,35.59) 14.231,35.456 cw(c14.2,35.25) 14.407,35.219 14.349,33.557 ccw(c15.063,33.508) 15.014,32.794 15.159,32.794
  region net M_A: 2.012,29.934 2.012,32.766 cw(c4.552,32.766) 4.552,35.306 9.398,35.306 ccw(c9.398,36.576) 10.668,36.576 cw(c11.049,36.576) 11.049,36.957 13.081,36.957 cw(c13.081,36.83) 13.208,36.83 13.208,34.798 ccw(c13.462,34.798) 13.462,34.544 cw(c13.462,34.128) 13.878,34.128 13.878,33.512 cw(c13.132,33.512) 13.132,32.766 6.745,32.766 ccw(c6.745,32.047) 6.026,32.047 6.026,29.934
  region net M_C: 17.082,34.276 cw(c17.083,33.579) 17.78,33.58 17.78,33.239 ccw(c19.581,35.04) 19.581,32.493 24.587,32.493 cw(c24.587,30.734) 26.346,30.734 cw(c25.608,30.734) 25.608,29.997 21.348,29.997 cw(c21.348,32.536) 19.767,30.548 ccw(c18.44,28.611) 18.007,30.919 cw(c18.221,32.82) 16.383,32.289 16.383,33.577 cw(c17.082,33.577)
  region net M_B: 15.082,34.29 cw(c15.098,33.513) 15.875,33.527 16.023,31.621 cw(c14.746,30.917) 16.186,31.147 16.186,30.734 cw(c14.662,30.734) 14.662,29.21 12.319,29.21 cw(c12.319,29.972) 11.557,29.972 11.557,30.734 cw(c11.938,30.734) 11.938,31.115 13.208,31.115 ccw(c13.144,32.195) 14.224,32.258 14.351,33.559 cw(c15.082,33.559)
  region: 14.161,36.722

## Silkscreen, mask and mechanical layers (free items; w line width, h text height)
Top Overlay:
  region: 35.052,5.334 35.052,2.032 35.56,3.683
  text "20250318 / TFoc1-1.1.0" at 8.255,30.099 h1.52
Bottom Overlay:
  region: 35.052,2.032 35.052,5.334 35.56,3.683
  text "SO1" at 37.579,15.367 h1
  text "SO2" at 22.733,15.05 h1
Mechanical 1:
  lines w0.254: 0,1.905 0,38 cw(c2,38) 2,40 38.105,40 ; 0,2 ccw(c2,2) 2,0 ; 1.905,0 38,0 ccw(c38,2) 40,2 40,38.105 ; 38,40 cw(c38,38) 40,38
